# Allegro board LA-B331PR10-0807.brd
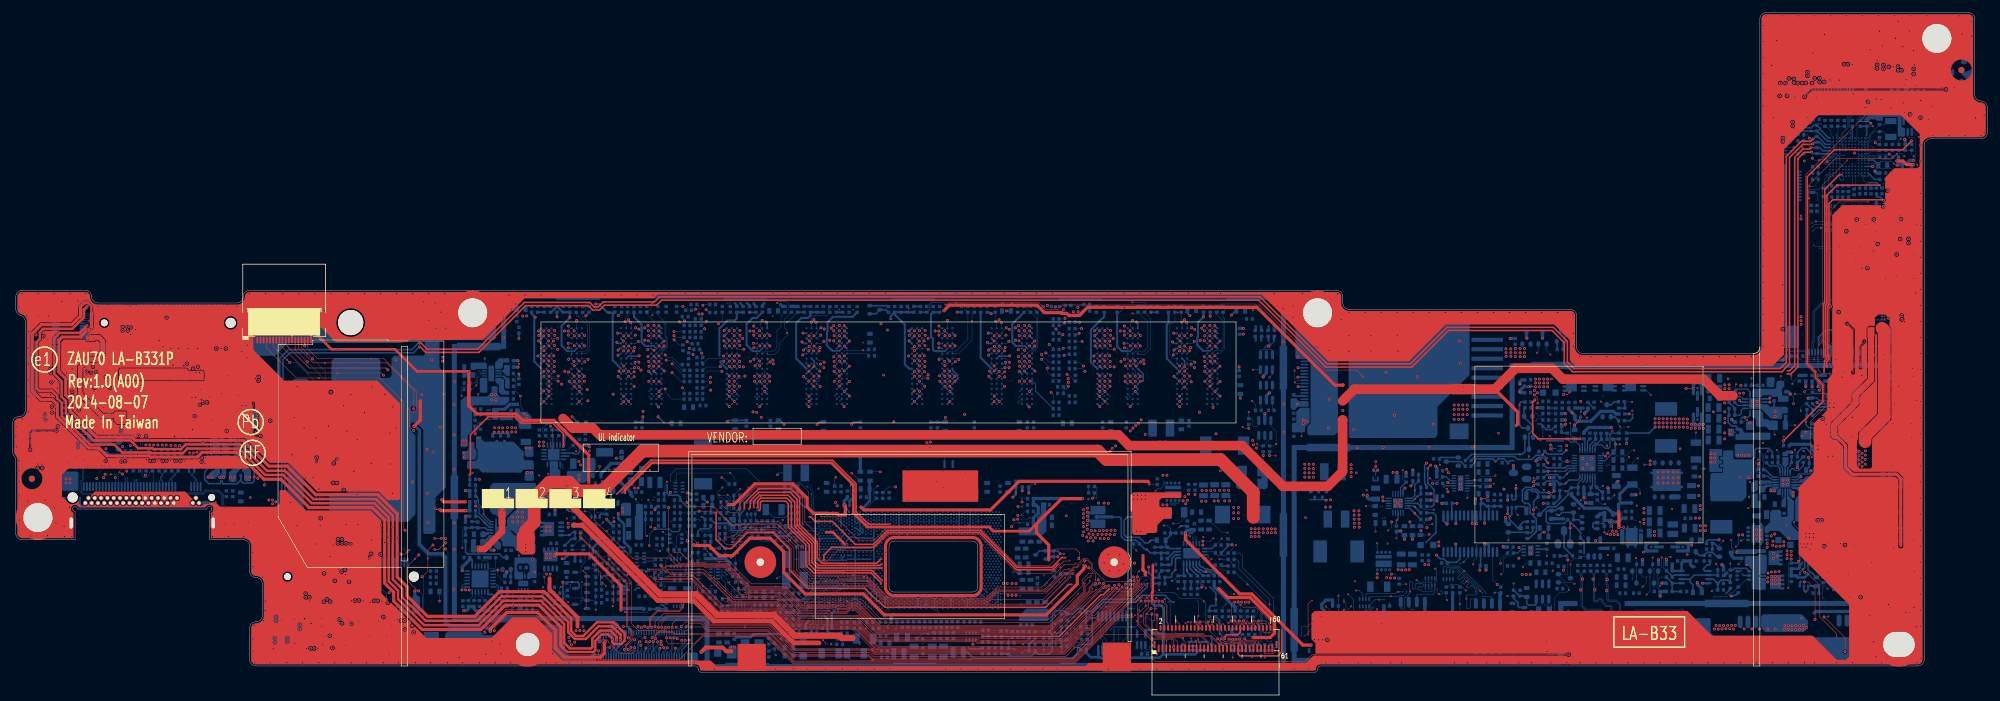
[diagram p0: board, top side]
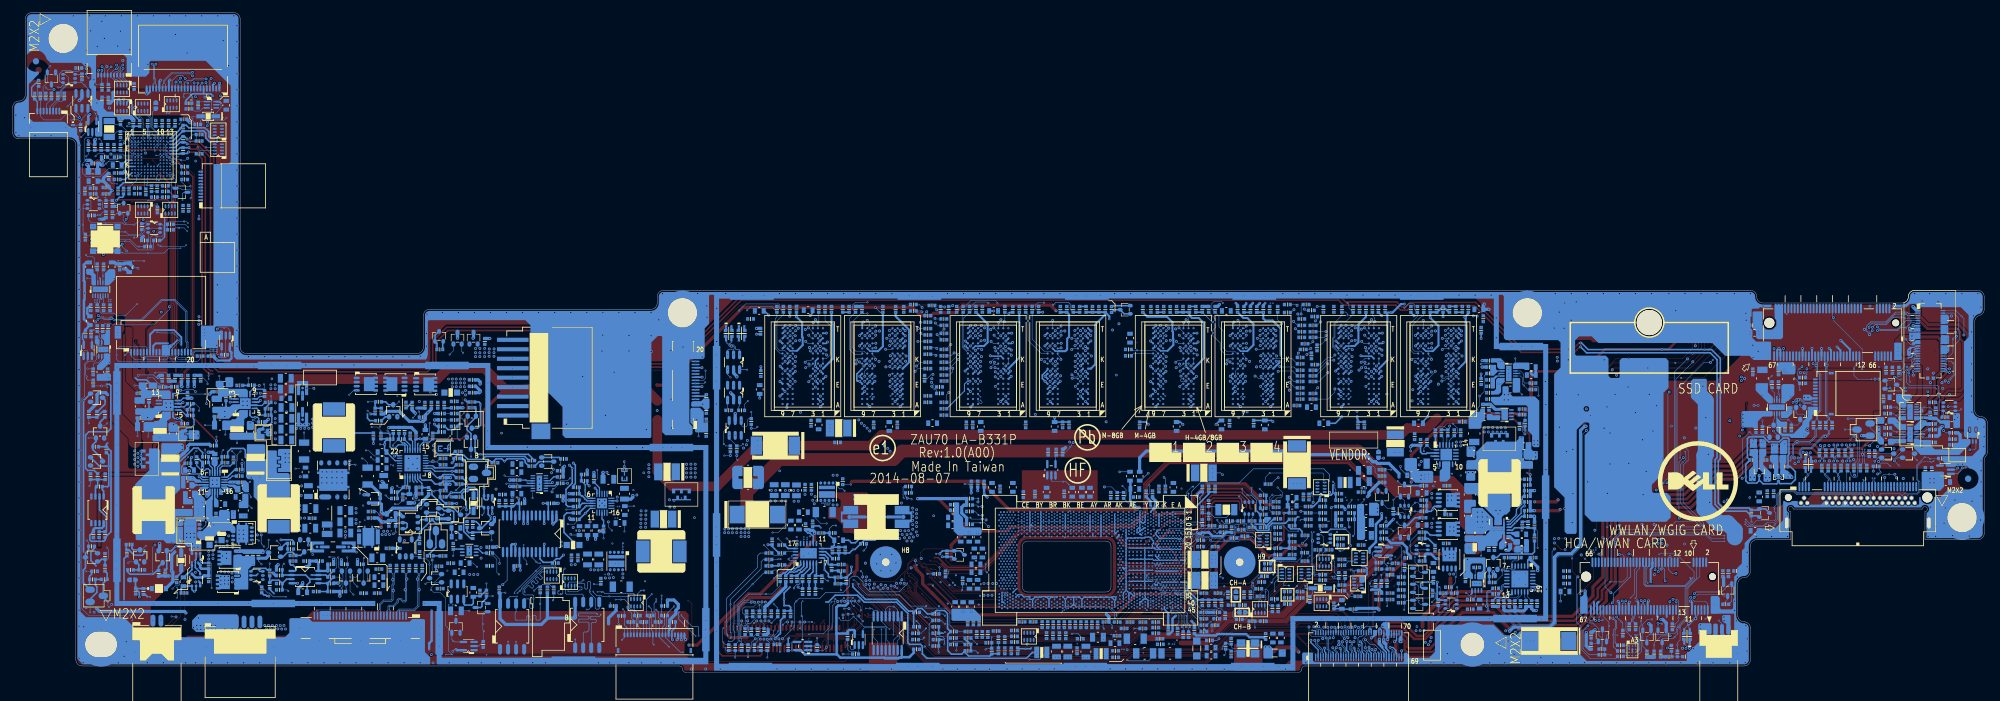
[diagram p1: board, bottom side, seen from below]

Outline 312.5 x 104.5 mm; copper layers: TOP, GND1, IN1, VCC, IN2, IN3, GND2, IN4, GND3, BOTTOM. Coordinates in mm from the lower left corner of the outline.
Outline path: 0,39.5 0,34.91 arc(0.06,34.56) 0.25,34.25 arc(0.44,33.94) 0.5,33.59 0.5,22 arc(0.79,21.29) 1.5,21 9.88,21 9.88,25.46 arc(9.59,26.14) 10.28,25.86 30.73,25.86 arc(31.41,26.14) 31.13,25.46 31.13,21 36.5,21 arc(37.21,20.71) 37.5,20 37.5,16 arc(37.79,15.29) 38.5,15 arc(39.21,14.71) 39.5,14 39.5,9 arc(39.21,8.29) 38.5,8 arc(37.79,7.71) 37.5,7 37.5,2 arc(37.79,1.29) 38.5,1 108,1 arc(108.35,0.85) 108.5,0.5 arc(108.65,0.15) 109,0 206,0 arc(206.35,0.15) 206.5,0.5 arc(206.65,0.85) 207,1 301.5,1 arc(302.21,1.29) 302.5,2 302.5,83.5 arc(302.79,84.21) 303.5,84.5 311.5,84.5 arc(312.21,84.79) 312.5,85.5 312.5,89.5 arc(312.21,90.21) 311.5,90.5 arc(310.79,90.79) 310.5,91.5 310.5,103.5 arc(310.21,104.21) 309.5,104.5 277.5,104.5 arc(276.79,104.21) 276.5,103.5 276.5,51.5 arc(276.21,50.79) 275.5,50.5 248.5,50.5 arc(247.79,50.79) 247.5,51.5 247.5,56.5 arc(247.21,57.21) 246.5,57.5 211.5,57.5 arc(210.79,57.79) 210.5,58.5 210.5,59.5 arc(210.21,60.21) 209.5,60.5 37.5,60.5 arc(36.79,60.21) 36.5,59.5 arc(36.21,58.79) 35.5,58.5 13.5,58.5 arc(12.79,58.79) 12.5,59.5 arc(12.21,60.21) 11.5,60.5 1.5,60.5 arc(0.79,60.21) 0.5,59.5 0.5,57.5 arc(0.71,56.89) 1.25,56.53 arc(1.79,56.18) 2,55.56 2,41.5 arc(1.71,40.79) 1,40.5 arc(0.29,40.21) 0,39.5 ; 138.69,19.97 arc(138.92,20.55) 139.5,20.79 151.9,20.79 arc(152.47,20.55) 152.71,19.97 152.71,13.53 arc(152.47,12.95) 151.9,12.71 139.5,12.71 arc(138.92,12.95) 138.69,13.53 138.69,19.97

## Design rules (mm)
net group DDRCTL_8.5/8.5/7/7/8.5/8.5_16_25: nets M_ODT0 M_ODT2
net group DIFFPAIR0: nets ALS_SMBCLK ALS_SMBDATA
net group DIFFPAIR1: nets CHARGER_SCL CHARGER_SDA
net group DIFFPAIR2: nets CHARGER_SMBCLK CHARGER_SMBDAT
net group DIFFPAIR3: nets CL_CLK CL_DATA
net group DIFFPAIR4: nets CL_CLK_R CL_DATA_R
net group DIFFPAIR6: nets EC_SMCA EC_SMDA
net group DIFFPAIR11: nets PBAT_SMBCLK PBAT_SMBDAT
net group DIFFPAIR12: nets PCH_DDI1_CLK PCH_DDI1_DAT
net group DIFFPAIR13: nets PCH_DDI2_CLK PCH_DDI2_DAT
net group DIFFPAIR14: nets PCH_SMBCLK PCH_SMBDATA
net group DIFFPAIR15: nets SENSOR_I2C_SCL SENSOR_I2C_SDA
net group DIFFPAIR16: nets SMBCLK SMBDATA
net group DIFFPAIR17: nets SML0CLK SML0DATA
net group DIFFPAIR18: nets SML1CLK SML1DATA
net group DIFFPAIR19: nets SML1_SMBCLK SML1_SMBDATA
net group DIFFPAIR20: nets USH_SMBCLK USH_SMBDAT
net group DIFFPAIR22: nets BASE_SMBCLK BASE_SMBDAT
net group EDP_AUX_CONN: nets EDP_AUXN_CONN EDP_AUXP_CONN
net group EDP_TX_P0_CONN: nets EDP_TXN_P0_CONN EDP_TXP_P0_CONN
net group EDP_TX_P1_CONN: nets EDP_TXN_P1_CONN EDP_TXP_P1_CONN
net group PCH_DDI1_0: nets PCH_DDI1_N0 PCH_DDI1_P0
net group PCH_DDI1_1: nets PCH_DDI1_N1 PCH_DDI1_P1
net group PCH_DDI1_2: nets PCH_DDI1_N2 PCH_DDI1_P2
net group PCH_DDI1_3: nets PCH_DDI1_N3 PCH_DDI1_P3
net group PCH_DDI1_AUX: nets PCH_DDI1_AUXN PCH_DDI1_AUXP
net group PCH_DDI2_0_C: nets PCH_DDI2_N0_C PCH_DDI2_P0_C
net group PCH_DDI2_1_C: nets PCH_DDI2_N1_C PCH_DDI2_P1_C
net group PCH_DDI2_2_C: nets PCH_DDI2_N2_C PCH_DDI2_P2_C
net group PCH_DDI2_3_C: nets PCH_DDI2_N3_C PCH_DDI2_P3_C
net group PCH_DDI2_AUX_C: nets PCH_DDI2_AUXN_C PCH_DDI2_AUXP_C
net group PCIE: nets PCIE_PTX_DRX_N5 PCIE_PTX_DRX_P5
net group PCIE_PRX_DTX_5: nets PCIE_PRX_DTX_N5 PCIE_PRX_DTX_P5
net group PCIE_PTX_DRX_3: nets PCIE_PTX_DRX_N3 PCIE_PTX_DRX_P3
net group PCIE_PTX_DRX_6: nets PCIE_PTX_DRX_N6 PCIE_PTX_DRX_P6
net group PCIE_PTX_DRX_6_C: nets PCIE_PTX_DRX_N6_C PCIE_PTX_DRX_P6_C
net group SATA_R1: nets SATA_RN1 SATA_RP1
net group SATA_R1_C: nets SATA_RN1_C SATA_RP1_C
net group SATA_T1: nets SATA_TN1 SATA_TP1
net group SATA_T1_C: nets SATA_TN1_C SATA_TP1_C
net group USB20_0: nets USB20_N0 USB20_P0
net group USB20_1: nets USB20_N1 USB20_P1
net group USB20_5_R: nets USB20_N5_R USB20_P5_R
net group USB20_P6_R: nets USB20_N6_R USB20_P6_R
net group 10: nets LINE1_L LINE1_R REM_DIODE1_N REM_DIODE1_P REM_DIODE2_N REM_DIODE2_P REM_DIODE3_N REM_DIODE3_P XTAL24_IN XTAL24_OUT
net group 12: nets +SIM_PWR CLK_LPC_DEBUG CLK_PCI_MEC CLKOUT_LPC0 CLKOUT_LPC1 HDA_BIT_CLK MSCLK SATA_RCOMP SUSCLK SYSCLK VCCSENSE VCCSENSE_R VSSSENSE VSSSENSE_R XCLK_BIASREF
net group 15: nets PCH_OPIRCOMP PCH_RTCRST# PCH_RTCX1 PCH_RTCX2 PCH_SPI_CLK PCH_SRTCRST# SPI_CLK_ROM1 SPI_CLK_ROM2 SPI_PCH_CLK TPM_SPI_CLK USBRBIAS
net group 20: nets BASE_DC_IN_SS
net group 50H: nets GNSS_SCL GNSS_SDA H_CATERR# H_PROCHOT# H_PROCHOT#_R I2C0_SDA I2C1_SCK I2C1_SDA I2S_MCLK I2S_SCLK PCH_PLTRST# PLT_RST# VCCSTPG_MCP XDP_BPM0# XDP_BPM1# XDP_PWRGD
net group DIFFPAIR23: nets MSDATA
net group GND: nets AGND
net group I2S: nets HDA_RST# HDA_SDOUT HDA_SYNC I2S_SDIN0 I2S_SDOUT I2S_SFRM
net group MG_DATA_DQ-DQ[A_DQ0][0~250MIL]: nets DDR_A_D0 DDR_A_D1 DDR_A_D2 DDR_A_D3 DDR_A_D4 DDR_A_D5 DDR_A_D6 DDR_A_D7
net group MG_DATA_DQ-DQS[A_DQ-DQS0][-400~100MIL]: nets DDR_A_DQS0
net group MG_DATA_DQ-DQS[A_DQ-DQS1][-400~100MIL]: nets DDR_A_DQS1
net group MG_DATA_DQ-DQS[A_DQ-DQS2][-400~100MIL]: nets DDR_A_DQS2
net group MG_DATA_DQ-DQS[A_DQ-DQS3][-400~100MIL]: nets DDR_A_DQS3
net group MG_DATA_DQ-DQS[A_DQ-DQS4][-400~100MIL]: nets DDR_A_DQS4
net group MG_DATA_DQ-DQS[A_DQ-DQS5][-400~100MIL]: nets DDR_A_D40 DDR_A_D41 DDR_A_D42 DDR_A_D43 DDR_A_D44 DDR_A_D45 DDR_A_D46 DDR_A_D47 DDR_A_DQS5
net group MG_DATA_DQ-DQS[A_DQ-DQS6][-400~100MIL]: nets DDR_A_DQS6
net group MG_DATA_DQ-DQS[A_DQ-DQS7][-400~100MIL]: nets DDR_A_DQS7
net group MG_DATA_DQ-DQS[A_DQ-DQS#0][-400~100MIL]: nets DDR_A_DQS#0
net group MG_DATA_DQ-DQS[A_DQ-DQS#1][-400~100MIL]: nets DDR_A_D8 DDR_A_D9 DDR_A_D10 DDR_A_D11 DDR_A_D12 DDR_A_D13 DDR_A_D14 DDR_A_D15 DDR_A_DQS#1
net group MG_DATA_DQ-DQS[A_DQ-DQS#2][-400~100MIL]: nets DDR_A_D16 DDR_A_D17 DDR_A_D18 DDR_A_D19 DDR_A_D20 DDR_A_D21 DDR_A_D22 DDR_A_D23 DDR_A_DQS#2
net group MG_DATA_DQ-DQS[A_DQ-DQS#3][-400~100MIL]: nets DDR_A_D24 DDR_A_D25 DDR_A_D26 DDR_A_D27 DDR_A_D28 DDR_A_D29 DDR_A_D30 DDR_A_D31 DDR_A_DQS#3
net group MG_DATA_DQ-DQS[A_DQ-DQS#4][-400~100MIL]: nets DDR_A_D32 DDR_A_D33 DDR_A_D34 DDR_A_D35 DDR_A_D36 DDR_A_D37 DDR_A_D38 DDR_A_D39 DDR_A_DQS#4
net group MG_DATA_DQ-DQS[A_DQ-DQS#5][-400~100MIL]: nets DDR_A_DQS#5
net group MG_DATA_DQ-DQS[A_DQ-DQS#6][-400~100MIL]: nets DDR_A_D48 DDR_A_D49 DDR_A_D50 DDR_A_D51 DDR_A_D52 DDR_A_D53 DDR_A_D54 DDR_A_D55 DDR_A_DQS#6
net group MG_DATA_DQ-DQS[A_DQ-DQS#7][-400~100MIL]: nets DDR_A_D56 DDR_A_D57 DDR_A_D58 DDR_A_D59 DDR_A_D60 DDR_A_D61 DDR_A_D62 DDR_A_D63 DDR_A_DQS#7
net group MG_DATA_DQ-DQS[B_DQ-DQS0][-400~100MIL]: nets DDR_B_DQS0
net group MG_DATA_DQ-DQS[B_DQ-DQS1][-400~100MIL]: nets DDR_B_DQS1
net group MG_DATA_DQ-DQS[B_DQ-DQS2][-400~100MIL]: nets DDR_B_DQS2
net group MG_DATA_DQ-DQS[B_DQ-DQS3][-400~100MIL]: nets DDR_B_DQS3
net group MG_DATA_DQ-DQS[B_DQ-DQS4][-400~100MIL]: nets DDR_B_DQS4
net group MG_DATA_DQ-DQS[B_DQ-DQS5][-400~100MIL]: nets DDR_B_D40 DDR_B_D41 DDR_B_D42 DDR_B_D43 DDR_B_D44 DDR_B_D45 DDR_B_D46 DDR_B_D47 DDR_B_DQS5
net group MG_DATA_DQ-DQS[B_DQ-DQS6][-400~100MIL]: nets DDR_B_DQS6
net group MG_DATA_DQ-DQS[B_DQ-DQS7][-400~100MIL]: nets DDR_B_DQS7
net group MG_DATA_DQ-DQS[B_DQ-DQS#0][-400~100MIL]: nets DDR_B_D0 DDR_B_D1 DDR_B_D2 DDR_B_D3 DDR_B_D4 DDR_B_D5 DDR_B_D6 DDR_B_D7 DDR_B_DQS#0
net group MG_DATA_DQ-DQS[B_DQ-DQS#1][-400~100MIL]: nets DDR_B_D8 DDR_B_D9 DDR_B_D10 DDR_B_D11 DDR_B_D12 DDR_B_D13 DDR_B_D14 DDR_B_D15 DDR_B_DQS#1
net group MG_DATA_DQ-DQS[B_DQ-DQS#2][-400~100MIL]: nets DDR_B_D16 DDR_B_D17 DDR_B_D18 DDR_B_D19 DDR_B_D20 DDR_B_D21 DDR_B_D22 DDR_B_D23 DDR_B_DQS#2
net group MG_DATA_DQ-DQS[B_DQ-DQS#3][-400~100MIL]: nets DDR_B_D24 DDR_B_D25 DDR_B_D26 DDR_B_D27 DDR_B_D28 DDR_B_D29 DDR_B_D30 DDR_B_D31 DDR_B_DQS#3
net group MG_DATA_DQ-DQS[B_DQ-DQS#4][-400~100MIL]: nets DDR_B_D32 DDR_B_D33 DDR_B_D34 DDR_B_D35 DDR_B_D36 DDR_B_D37 DDR_B_D38 DDR_B_D39 DDR_B_DQS#4
net group MG_DATA_DQ-DQS[B_DQ-DQS#5][-400~100MIL]: nets DDR_B_DQS#5
net group MG_DATA_DQ-DQS[B_DQ-DQS#6][-400~100MIL]: nets DDR_B_D48 DDR_B_D49 DDR_B_D50 DDR_B_D51 DDR_B_D52 DDR_B_D53 DDR_B_D54 DDR_B_D55 DDR_B_DQS#6
net group MG_DATA_DQ-DQS[B_DQ-DQS#7][-400~100MIL]: nets DDR_B_D56 DDR_B_D57 DDR_B_D58 DDR_B_D59 DDR_B_D60 DDR_B_D61 DDR_B_D62 DDR_B_D63 DDR_B_DQS#7
net group MG_STROBE_CK-DQS[A_CK0-DQS][-1500~2500MILMIL]: nets M_CLK_A_DDR0
net group MG_STROBE_CK-DQS[A_CK#0-DQS][-1500~2500MILMIL]: nets M_CLK_A_DDR#0
net group MG_STROBE_CK-DQS[B_CK0-DQS][-1500~2500MILMIL]: nets M_CLK_B_DDR0
net group MG_STROBE_CK-DQS[B_CK#0-DQS][-1500~2500MILMIL]: nets M_CLK_B_DDR#0
net group POWER-10: nets +1.05VS_VCCST +3V_PCH_DSW +PCH_VCCDSW +V1.05A_DCPSUS1 +V1.05A_DCPSUS2 +V1.05A_DCPSUS3 +V1.05S_APLL +V1.05S_APLLOPI +V1.05S_AUSB +VCCIO_OUT +VR_CAP +VS_LPSS_SDIO V_DDR_REFA_R V_DDR_REFB_R
net group POWER-15: nets +V1.05S_AUSB3PLL +V1.05S_MPHY_PCIE CFG_RCOMP PCIE_RCOMP PROC_OPI_COMP SM_RCOMP0 SM_RCOMP1 SM_RCOMP2 TD_IREF
net group POWER-20: nets +1.5VS +1.5VSP +5VS_AUDIO +EDP_COM +VCCIOA_OUT
net group SIM: nets UIM_CLK UIM_DATA UIM_DET# UIM_RESET
net group SPI: nets PCH_SPI_CS0# PCH_SPI_CS1# PCH_SPI_CS2# PCH_SPI_IO2 PCH_SPI_IO3 PCH_SPI_SI PCH_SPI_SO SPI_IO2_ROM1 SPI_IO2_ROM2 SPI_IO3_ROM1 SPI_IO3_ROM2 SPI_PCH_CS0# SPI_PCH_CS1# SPI_PCH_IO2 SPI_PCH_IO3 SPI_PCH_SI SPI_PCH_SO SPI_SI_ROM1 SPI_SI_ROM2 SPI_SO_ROM1 SPI_SO_ROM2 TPM_SPI_SI TPM_SPI_SO
net group SPK: nets SPK_L+_C SPK_L-_C SPK_R+_C SPK_R-_C
net group SVID: nets H_CPU_SVIDALRT# H_CPU_SVIDCLK H_CPU_SVIDDAT VR_SVID_ALRT# VR_SVID_CLK VR_SVID_DAT
net group USB30: nets USB3RN1 USB3RN1_C USB3RN1_RP USB3RP1 USB3RP1_C USB3RP1_RP USB3TN1 USB3TP1
nets with their own width: min track width 0.203; nets +3.3V_M +3VALW_EC +3VNS_PWR +3VS_AUDIO +3VS_TS
nets with their own width: min track width 0.254; nets +1.05V_SATAMODPHY_D +1.05VDX_MODPHY_D +1.05VS +1.05VS_XDP +1.35V_DDR +1.35VP +3VS_TPM +RTC_VCCSUS +RTCVCC +RTCVCC_R +V1.05A_AOSCSUS +V1.05S_AXCK_DCB +V1.05S_AXCK_LCPLL +V1.05S_MPHY_SATA +V1.05S_MPHY_USB3 ACAV_IN B+ BATT_PRS# BQ24777_REGN COMP CSSN_1 CSSP_1 FB HOT# I_ADP I_SYS IMON ISUMN ISUMP N45067794 N45067802 N45067875 N50817758 N50817763 N50817815 N50817876 N50817886 N50817889 N50817892 N50817943 N50817947 N52711885 N115444004 N115444070 N115444179 NTC PBAT_PRES# V_SYS VGATE VR_ON
nets with their own width: min track width 0.381; nets +LCDVDD +V1.05S_ASATA3PLL +VCHGR
nets with their own width: min track width 0.406; nets +3V_PCH
nets with their own width: min track width 0.508; nets +0.675VS +1.05VA +1.8VS +3VALW +3VS +5VALW +5VS +DC_IN +PBATT +VCC_CORE +VREFCA +VREFDQ_A +VREFDQ_B BATDRV# GND N50817748 N52697183 VBATT
nets with their own width: min track width 0.635; nets +1.05V_USB3MODPHY +5V_DOCK N53478114
nets with their own width: min track width 0.762; nets +1.05V_SATAMODPHY
nets with their own width: min track width 1.016; nets +1.05VDX_MODPHY +3.3VDX_SSD +3VS_CAM CHG_LGATE CHG_SW CHG_UGATE LAGTE LG_3V LG_5V LX_3V LX_5V PHASE UAGTE UG_3V UG_5V
nets with their own width: min track width 2.032; nets +3VS_WLAN
nets with their own width: min track width 2.54; nets +3VS_WWAN

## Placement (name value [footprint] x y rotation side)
C1  0.1U_0402_10V7K  [C_0402]  192.44 8.81 90 bottom
C2  0.1U_0402_10V7K  [C_0402]  193.08 3.45 90 bottom
C4  10U_0603_6.3V6M  [C_0603]  255.24 15.08 180 bottom
C5  .1U_0402_16V7K  [C_0402]  255.26 12.54 180 bottom
C6  10U_0603_6.3V6M  [C_0603]  255.24 13.81 180 bottom
C7  0.1U_0402_10V7K  [C_0402]  247.69 16.93 270 bottom
C8  0.1U_0402_10V7K  [C_0402]  248.7 16.93 270 bottom
C9  0.1U_0402_10V7K  [C_0402]  249.72 16.93 270 bottom
C10  0.1U_0402_10V7K  [C_0402]  250.73 16.93 270 bottom
C11  1U_0603_25V6K  [C_0603]  239.61 13.35 270 bottom
C12  0.1U_0402_25V6  [C_0402]  244.38 13.25 0 bottom
C13  0.1U_0402_10V7K  [C_0402]  251.75 16.93 270 bottom
C14  0.1U_0402_10V7K  [C_0402]  252.77 16.93 270 bottom
C16  22U_0603_6.3V6M  [C_0603]  36.1 27.08 90 bottom
C17  0.1U_0402_10V7K  [C_0402]  33.82 27.83 90 bottom
C18  22U_0603_6.3V6M  [C_0603]  7.3 30.15 180 bottom
C19  0.1U_0402_10V7K  [C_0402]  9.82 31.51 90 bottom
C20  22U_0603_6.3V6M  [C_0603]  37.46 22.41 180 bottom
C21  0.1U_0402_10V7K  [C_0402]  40.98 16.07 270 bottom
C22  22U_0603_6.3V6M  [C_0603]  66.14 12.79 0 bottom
C23  0.1U_0402_10V7K  [C_0402]  66.13 14.06 0 bottom
C29  .1U_0402_16V7K  [C_0402]  14.01 48.3 270 bottom
C30  47P_0402_50V8J  [C_0402]  15.02 48.3 270 bottom
C31  4.7U_0603_6.3V6K  [C_0603]  36.14 53.78 0 bottom
C32  0.01U_0402_16V7K  [C_0402]  36.66 54.96 0 bottom
C33  0.1U_0402_10V7K  [C_0402]  32.04 39.16 270 bottom
C34  4700P_0402_16V7K  [C_0402]  15.33 40.99 0 bottom
C35  0.1U_0402_10V7K  [C_0402]  33.06 48.05 270 bottom
C74  0.1U_0402_10V7K  [C_0402]  233.46 26.31 90 bottom
C75  4700P_0402_25V7K  [C_0402]  235.49 26.31 90 bottom
C76  2200P_0402_25V7K  [C_0402]  232.24 16.86 0 bottom
C77  2200P_0402_25V7K  [C_0402]  227.07 17.3 180 bottom
C78  2200P_0402_25V7K  [C_0402]  227.82 26.76 180 bottom
C79  0.1U_0402_10V7K  [C_0402]  232.4 26.76 180 bottom
C90  0.1U_0402_10V7K  [C_0402]  245.51 16.79 180 bottom
C92  1U_0402_6.3V6K  [C_0402]  234.53 28.16 0 bottom
C93  2200P_0402_25V7K  [C_0402]  232.24 29.43 0 bottom
C94  2200P_0402_25V7K  [C_0402]  232.24 30.45 0 bottom
C95  1U_0402_6.3V6K  [C_0402]  226.3 27.91 180 bottom
C96  1U_0402_6.3V6K  [C_0402]  37.12 48.05 270 bottom
C97  10U_0603_6.3V6M  [C_0603]  71.47 47.08 0 bottom
C98  2200P_0402_25V7K  [C_0402]  72.38 45.81 180 bottom
C99  2200P_0402_25V7K  [C_0402]  72.38 44.8 180 bottom
C100  0.1U_0402_10V7K  [C_0402]  78.32 49.37 0 bottom
C101  0.1U_0402_10V7K  [C_0402]  300.14 58.21 270 bottom
C102  0.1U_0402_10V7K  [C_0402]  9.05 41.19 270 bottom
C103  1U_0402_6.3V6K  [C_0402]  78.32 43.27 0 bottom
C104  2200P_0402_25V7K  [C_0402]  299.12 63.77 90 bottom
C105  2200P_0402_25V7K  [C_0402]  298.11 63.77 90 bottom
C106  0.1U_0402_10V7K  [C_0402]  89.7 35.96 90 bottom
C107  10U_0603_6.3V6M  [C_0603]  90.4 31.21 0 bottom
C108  1000P_0402_25V8J  [C_0402]  86.4 37.48 90 bottom
C109  0.1U_0402_10V7K  [C_0402]  83.35 37.48 90 bottom
C110  0.1U_0402_10V7K  [C_0402]  297.09 58.21 270 bottom
C111  1000P_0402_50V7K  [C_0402]  88.68 35.96 90 bottom
C112  0.1U_0402_10V7K  [C_0402]  300.98 54.08 270 bottom
C113  2200P_0402_25V7K  [C_0402]  34.07 45.1 90 bottom
C114  2200P_0402_25V7K  [C_0402]  33.06 45.1 90 bottom
C115  0.1U_0402_10V7K  [C_0402]  237.48 16.86 180 bottom
C116  0.1U_0402_10V7K  [C_0402]  36.61 38.91 270 bottom
C117  0.1U_0402_10V7K  [C_0402]  226.3 31.92 180 bottom
C118  0.1U_0402_10V7K  [C_0402]  9.13 39.34 180 bottom
C119  10U_0603_6.3V6M  [C_0603]  233.4 32.99 180 bottom
C120  0.1U_0402_10V7K  [C_0402]  242.72 17.28 0 bottom
C121  2200P_0402_25V7K  [C_0402]  242.78 19.5 90 bottom
C122  0.1U_0402_10V7K  [C_0402]  85.08 29.56 0 bottom
C123  10U_0603_6.3V6M  [C_0603]  88.75 28.41 0 bottom
C124  0.047U_0402_25V7K  [C_0402]  88.73 27.27 0 bottom
C125  0.1U_0402_10V7K  [C_0402]  84.92 24.99 0 bottom
C126  10U_0603_6.3V6M  [C_0603]  88.75 23.33 0 bottom
C127  0.047U_0402_25V7K  [C_0402]  87.41 20.11 270 bottom
C128  0.1U_0402_10V7K  [C_0402]  85.18 20.41 0 bottom
C129  10U_0603_6.3V6M  [C_0603]  87.67 15.91 90 bottom
C130  0.047U_0402_25V7K  [C_0402]  84.82 13.48 0 bottom
C131  0.1U_0402_10V7K  [C_0402]  9.13 42.77 180 bottom
C132  1000P_0402_25V8J  [C_0402]  15.33 37.69 0 bottom
C133  2200P_0402_25V7K  [C_0402]  15.33 42 0 bottom
C134  0.1U_0402_10V7K  [C_0402]  16.43 43.78 270 bottom
C135  220P_0402_25V8K  [C_0402]  15.33 38.7 0 bottom
C136  0.1U_0402_10V7K  [C_0402]  9.13 36.42 180 bottom
C139  0.1U_0402_10V7K  [C_0402]  299.04 80.61 0 bottom
C140  0.1U_0402_10V7K  [C_0402]  292.31 75.81 0 bottom
C141  0.1U_0402_10V7K  [C_0402]  295.49 79.09 0 bottom
C142  0.1U_0402_10V7K  [C_0402]  283.45 82.14 180 bottom
C143  0.1U_0402_10V7K  [C_0402]  297.27 76.8 0 bottom
C144  0.1U_0402_10V7K  [C_0402]  287.87 76.17 0 bottom
C145  0.1U_0402_10V7K  [C_0402]  297.27 75.79 0 bottom
C146  0.1U_0402_10V7K  [C_0402]  292.31 76.7 0 bottom
C147  0.1U_0402_10V7K  [C_0402]  291.12 86.5 90 bottom
C148  0.1U_0402_10V7K  [C_0402]  287.82 86.5 90 bottom
C149  0.1U_0402_10V7K  [C_0402]  293.41 86.5 90 bottom
C150  4700P_0402_25V7K  [C_0402]  295.49 81.63 0 bottom
C154  2200P_0402_50V7K  [C_0402]  285.53 82.19 90 bottom
C155  2200P_0402_50V7K  [C_0402]  285.53 84.88 270 bottom
C156  2200P_0402_50V7K  [C_0402]  285.53 85.74 90 bottom
C157  22P_0402_50V8J  [C_0402]  295.44 86.76 90 bottom
C158  27P_0402_50V8J  [C_0402]  295.44 85.64 270 bottom
C159  0.1U_0402_10V7K  [C_0402]  283.45 84.17 180 bottom
C160  4.7U_0603_6.3V6K  [C_0603]  295.25 80.36 0 bottom
C161  1U_0402_6.3V4Z  [C_0402]  288.83 86.5 90 bottom
C162  4.7P_0402_50V8C  [C_0402]  289.63 76.15 90 bottom
C163  100P_0402_50V8J  [C_0402]  244.43 51.15 0 bottom
C164  100P_0402_50V8J  [C_0402]  164.63 18.31 90 bottom
C165  0.1U_0402_25V6K  [C_0402]  297.72 74.72 270 bottom
C166  100P_0402_50V8J  [C_0402]  37.37 25.7 270 bottom
C168  100P_0402_50V8J  [C_0402]  138.59 57.02 90 bottom
C193  .1U_0402_16V7K  [C_0402]  202.73 43.05 90 bottom
C194  .1U_0402_16V7K  [C_0402]  202.74 39.19 90 bottom
C197  0.1U_0402_10V7K  [C_0402]  78.32 44.29 0 bottom
C198  0.1U_0402_10V7K  [C_0402]  295.57 64.69 270 bottom
C199  0.1U_0402_10V7K  [C_0402]  5.04 36.03 0 bottom
C200  10P_0402_50V8J  [C_0402]  5.95 36.92 180 bottom
C203  0.1U_0402_10V7K  [C_0402]  55.66 6.75 90 bottom
C204  0.1U_0402_10V7K  [C_0402]  56.68 6.75 90 bottom
C205  0.47U_0402_6.3V6K  [C_0402]  115.05 26 180 bottom
C214  .1U_0402_16V7K  [C_0402]  252.47 19.64 0 bottom
C215  .1U_0402_16V7K  [C_0402]  255 16.35 180 bottom
C216  470U_X_2VY_R9M  [C_X]  109.26 35.86 270 bottom
C217  470U_X_2VY_R9M  [C_X]  188.81 35.91 0 bottom
C218  2200P_0402_25V7K  [C_0402]  299.76 48.05 270 bottom
C219  0.1U_0402_10V7K  [C_0402]  297.47 47.13 90 bottom
C220  0.1U_0402_10V7K  [C_0402]  297.37 53.99 90 bottom
C221  330U_B2_2.5VM_R9M  [C_B2]  125.19 17.87 0 bottom
C222  330U_B2_2.5VM_R9M  [C_B2]  125.19 14.57 0 bottom
C223  330U_B2_2.5VM_R9M  [C_B2]  125.36 31.59 0 bottom
C224  100P_0402_50V8J  [C_0402]  138.72 27.58 90 bottom
C225  100P_0402_50V8J  [C_0402]  153.5 5.71 0 bottom
C234  0.1U_0402_16V4Z  [C_0402]  78.28 11.34 270 bottom
C235  0.01U_0402_16V7K  [C_0402]  72.34 18.16 180 bottom
C236  0.1U_0402_10V7K  [C_0402]  77.35 13.31 0 bottom
C237  0.1U_0402_10V7K  [C_0402]  77.34 12.42 0 bottom
C238  2200P_0402_25V7K  [C_0402]  81.37 11.52 0 bottom
C239  0.1U_0402_10V7K  [C_0402]  81.37 10 0 bottom
C240  0.1U_0402_10V7K  [C_0402]  82.59 15.28 270 bottom
C241  1U_0402_6.3V6K  [C_0402]  284.15 89.26 0 bottom
C242  33P_0402_50V8J  [C_0402]  256.5 12.54 0 bottom
C243  33P_0402_50V8J  [C_0402]  202.73 41.94 270 bottom
C244  .1U_0402_16V7K  [C_0402]  202.75 38.3 270 bottom
C245  15P_0402_50V8J  [C_0402]  8.8 31.51 90 bottom
C246  15P_0402_50V8J  [C_0402]  34.83 27.83 90 bottom
C247  33P_0402_50V8J  [C_0402]  41.86 16.07 270 bottom
C248  33P_0402_50V8J  [C_0402]  66.13 15.08 0 bottom
C249  33P_0402_50V8J  [C_0402]  16.04 48.3 270 bottom
C250  33P_0402_50V8J  [C_0402]  234.48 26.31 90 bottom
C251  33P_0402_50V8J  [C_0402]  285.79 47.03 270 bottom
C252  33P_0402_50V8J  [C_0402]  284.77 47.03 270 bottom
C253  33P_0402_50V8J  [C_0402]  283.75 47.03 270 bottom
C255  10U_0603_6.3V6M  [C_0603]  278.7 90.53 270 bottom
C256  0.1U_0402_10V7K  [C_0402]  289.6 72.79 90 bottom
C257  0.1U_0402_10V7K  [C_0402]  295.82 76.71 270 bottom
C258  0.1U_0402_10V7K  [C_0402]  295.49 78.07 0 bottom
C259  0.1U_0402_10V7K  [C_0402]  294.08 76.71 270 bottom
C260  330U_D2E_6.3VM_R25M  [C_D2E]  66.25 4.95 0 bottom
C261  0.22U_0402_10V6K  [C_0402]  283.14 90.31 270 bottom
C262  1U_0402_6.3V6K  [C_0402]  309.01 90.82 90 bottom
C263  0.1U_0402_10V7K  [C_0402]  74.04 39.41 270 bottom
C264  2200P_0402_25V7K  [C_0402]  78.88 41.52 90 bottom
C265  0.1U_0402_10V7K  [C_0402]  79.79 41.52 90 bottom
C266  47P_0402_50V8J  [C_0402]  66.14 16.04 0 bottom
C267  47P_0402_50V8J  [C_0402]  40.13 16.05 180 bottom
C268  47P_0402_50V8J  [C_0402]  79.78 56.47 270 bottom
C269  47P_0402_50V8J  [C_0402]  90.64 37.79 270 bottom
C270  47P_0402_50V8J  [C_0402]  195.27 55.97 0 bottom
C271  47P_0402_50V8J  [C_0402]  181.49 36.42 0 bottom
C272  0.1U_0402_10V7K  [C_0402]  301.06 76.68 270 bottom
C273  0.1U_0402_10V7K  [C_0402]  48.21 2.47 180 bottom
CA53  1000P_0402_25V8J  [C_0402]  33.36 32.61 0 bottom
CA54  1000P_0402_25V8J  [C_0402]  32.5 32.61 180 bottom
CA55  1000P_0402_25V8J  [C_0402]  35.8 33.62 180 bottom
CA56  1000P_0402_25V8J  [C_0402]  36.66 33.62 0 bottom
CA57  27P_0402_50V8J  [C_0402]  29.69 45.77 180 bottom
CC1  0.1U_0402_10V7K  [C_0402]  148.63 34.42 90 bottom
CC2  10U_0603_6.3V6M  [C_0603]  144.82 27.83 90 bottom
CC3  10U_0603_6.3V6M  [C_0603]  157.52 28.59 90 bottom
CC4  10U_0603_6.3V6M  [C_0603]  143.29 27.83 90 bottom
CC5  10U_0603_6.3V6M  [C_0603]  148.88 27.83 90 bottom
CC6  10U_0603_6.3V6M  [C_0603]  142.02 27.83 90 bottom
CC7  10U_0603_6.3V6M  [C_0603]  154.21 28.59 90 bottom
CC8  2.2U_0402_6.3V6M  [C_0402]  146.09 27.81 90 bottom
CC9  2.2U_0402_6.3V6M  [C_0402]  156.25 28.58 90 bottom
CC10  2.2U_0402_6.3V6M  [C_0402]  152.56 27.69 90 bottom
CC11  2.2U_0402_6.3V6M  [C_0402]  150.72 27.76 90 bottom
CD1  .047U_0402_16V7K  [C_0402]  174.79 57.04 90 bottom
CD2  .047U_0402_16V7K  [C_0402]  188.45 57.07 90 bottom
CD3  .047U_0402_16V7K  [C_0402]  172.76 57.96 270 bottom
CD4  .047U_0402_16V7K  [C_0402]  182.92 57.96 270 bottom
CD5  0.1U_0402_25V6  [C_0402]  184.92 57.04 90 bottom
CD6  1U_0402_6.3V6K  [C_0402]  180.12 57.04 90 bottom
CD7  1U_0402_6.3V6K  [C_0402]  176.24 39.65 270 bottom
CD8  1U_0402_6.3V6K  [C_0402]  194.14 53.56 90 bottom
CD9  1U_0402_6.3V6K  [C_0402]  189.52 57.04 90 bottom
CD10  1U_0402_6.3V6K  [C_0402]  186.15 39.91 270 bottom
CD11  1U_0402_6.3V6K  [C_0402]  194.09 47.8 270 bottom
CD12  10U_0603_6.3V6M  [C_0603]  194.28 44.1 90 bottom
CD13  10U_0603_6.3V6M  [C_0603]  185.9 57.37 0 bottom
CD14  1U_0402_6.3V6K  [C_0402]  181.14 57.04 90 bottom
CD15  1U_0402_6.3V6K  [C_0402]  161.58 39.65 270 bottom
CD16  10U_0603_6.3V6M  [C_0603]  193.65 57.24 0 bottom
CD17  10U_0603_6.3V6M  [C_0603]  184.95 39.89 270 bottom
CD18  330U_B2_2VM_R15M  [C_B2]  180.4 38.69 180 bottom
CD19  .047U_0402_16V7K  [C_0402]  146.7 57.04 90 bottom
CD20  .047U_0402_16V7K  [C_0402]  145.68 57.04 90 bottom
CD21  .047U_0402_16V7K  [C_0402]  139.58 57.96 270 bottom
CD22  .047U_0402_16V7K  [C_0402]  153.2 57.96 270 bottom
CD23  0.1U_0402_25V6  [C_0402]  155.48 57.04 90 bottom
CD24  1U_0402_6.3V6K  [C_0402]  160.56 39.65 270 bottom
CD25  1U_0402_6.3V6K  [C_0402]  150.15 57.04 90 bottom
CD26  1U_0402_6.3V6K  [C_0402]  145.32 39.65 270 bottom
CD27  1U_0402_6.3V6K  [C_0402]  152.18 39.65 270 bottom
CD28  1U_0402_6.3V6K  [C_0402]  146.34 39.65 270 bottom
CD29  1U_0402_6.3V6K  [C_0402]  154.21 57.02 90 bottom
CD30  10U_0603_6.3V6M  [C_0603]  159.29 39.64 270 bottom
CD31  10U_0603_6.3V6M  [C_0603]  147.61 39.64 270 bottom
CD32  1U_0402_6.3V6K  [C_0402]  159.04 57.04 90 bottom
CD33  1U_0402_6.3V6K  [C_0402]  172.5 39.65 270 bottom
CD34  10U_0603_6.3V6M  [C_0603]  173.77 39.64 270 bottom
CD35  10U_0603_6.3V6M  [C_0603]  157.96 57.24 180 bottom
CD36  .047U_0402_16V7K  [C_0402]  133.64 57.02 90 bottom
CD37  .047U_0402_16V7K  [C_0402]  118.65 57.04 90 bottom
CD38  .047U_0402_16V7K  [C_0402]  114.59 57.94 270 bottom
CD39  .047U_0402_16V7K  [C_0402]  115.61 57.94 270 bottom
CD40  0.1U_0402_25V6  [C_0402]  129.32 57.02 90 bottom
CD41  1U_0402_6.3V6K  [C_0402]  119.92 39.91 270 bottom
CD42  1U_0402_6.3V6K  [C_0402]  116.62 57.02 90 bottom
CD43  1U_0402_6.3V6K  [C_0402]  134.15 39.65 270 bottom
CD44  1U_0402_6.3V6K  [C_0402]  130.34 57.04 90 bottom
CD45  1U_0402_6.3V6K  [C_0402]  117.64 57.02 90 bottom
CD46  1U_0402_6.3V6K  [C_0402]  116.11 39.91 270 bottom
CD47  10U_0603_6.3V6M  [C_0603]  119.73 57.24 0 bottom
CD48  10U_0603_6.3V6M  [C_0603]  128.31 39.64 270 bottom
CD49  1U_0402_6.3V6K  [C_0402]  131.35 57.02 90 bottom
CD50  1U_0402_6.3V6K  [C_0402]  132.37 57.04 90 bottom
CD51  10U_0603_6.3V6M  [C_0603]  121.19 39.89 270 bottom
CD52  10U_0603_6.3V6M  [C_0603]  135.67 52.23 90 bottom
CD53  330U_B2_2VM_R15M  [C_B2]  93.69 37.6 90 bottom
CD54  .047U_0402_16V7K  [C_0402]  98.33 57.02 90 bottom
CD55  .047U_0402_16V7K  [C_0402]  88.17 57.04 90 bottom
CD56  .047U_0402_16V7K  [C_0402]  95.29 57.96 270 bottom
CD57  .047U_0402_16V7K  [C_0402]  82.13 57.96 270 bottom
CD58  0.1U_0402_25V6  [C_0402]  97.32 57.04 90 bottom
CD59  1U_0402_6.3V6K  [C_0402]  99.35 57.04 90 bottom
CD60  1U_0402_6.3V6K  [C_0402]  83.55 39.7 180 bottom
CD61  1U_0402_6.3V6K  [C_0402]  80.11 53.72 90 bottom
CD62  1U_0402_6.3V6K  [C_0402]  80.11 46.51 270 bottom
CD63  1U_0402_6.3V6K  [C_0402]  96.37 57.02 90 bottom
CD64  1U_0402_6.3V6K  [C_0402]  98.59 39.65 270 bottom
CD65  10U_0603_6.3V6M  [C_0603]  81.18 57.5 180 bottom
CD66  10U_0603_6.3V6M  [C_0603]  89.32 39.45 0 bottom
CD67  1U_0402_6.3V6K  [C_0402]  99.6 39.65 270 bottom
CD68  1U_0402_6.3V6K  [C_0402]  91.22 57.04 90 bottom
CD69  10U_0603_6.3V6M  [C_0603]  104.31 39.45 0 bottom
CD70  10U_0603_6.3V6M  [C_0603]  114.34 39.89 270 bottom
CD71  .1U_0402_16V7K  [C_0402]  160.06 57.04 90 bottom
CD72  0.022U_0402_16V7K  [C_0402]  84.11 57.96 270 bottom
CD73  0.022U_0402_16V7K  [C_0402]  143.65 57.96 270 bottom
CD74  0.022U_0402_16V7K  [C_0402]  125.26 57.96 270 bottom
CD75  1U_0402_6.3V6K  [C_0402]  165.59 40.73 180 bottom
CD76  1U_0402_6.3V6K  [C_0402]  167.22 42.77 0 bottom
CD77  1U_0402_6.3V6K  [C_0402]  163.1 57.04 90 bottom
CD78  1U_0402_6.3V6K  [C_0402]  171.49 57.96 270 bottom
CD79  1U_0402_6.3V6K  [C_0402]  165.57 46.14 180 bottom
CD80  1U_0402_6.3V6K  [C_0402]  108.29 43.27 0 bottom
CD81  10U_0603_6.3V6M  [C_0603]  107.67 42 180 bottom
CD82  1U_0402_6.3V6K  [C_0402]  108.04 53.05 0 bottom
CD83  1U_0402_6.3V6K  [C_0402]  103.41 57.04 90 bottom
CD84  1U_0402_6.3V6K  [C_0402]  108.8 42.26 0 bottom
CD85  1U_0402_6.3V6K  [C_0402]  113.57 57.96 270 bottom
CD86  1U_0402_6.3V6K  [C_0402]  108.29 44.16 0 bottom
CD87  1U_0402_6.3V6K  [C_0402]  167.22 43.78 0 bottom
CD88  10U_0603_6.3V6M  [C_0603]  166.22 39.46 0 bottom
CH1  12P_0402_50V8J  [C_0402]  123.23 25.19 270 bottom
CH2  12P_0402_50V8J  [C_0402]  123.23 26.29 90 bottom
CH3  1U_0402_6.3V6K  [C_0402]  124.24 24.17 270 bottom
CH4  1U_0402_6.3V6K  [C_0402]  107.94 24.22 180 bottom
CH5  15P_0402_50V8J  [C_0402]  119.67 4.46 90 bottom
CH6  15P_0402_50V8J  [C_0402]  119.67 3.35 270 bottom
CH7  .1U_0402_16V7K  [C_0402]  227.87 12.59 90 bottom
CH8  .1U_0402_16V7K  [C_0402]  235.49 12.59 90 bottom
CH9  0.1U_0402_10V7K  [C_0402]  146.85 5.34 90 bottom
CH11  0.1U_0402_10V7K  [C_0402]  145.83 5.34 90 bottom
CH15  0.1U_0402_10V7K  [C_0402]  148.88 5.35 90 bottom
CH16  0.1U_0402_10V7K  [C_0402]  147.86 5.34 90 bottom
CH19  0.1U_0402_10V7K  [C_0402]  153.45 3.85 270 bottom
CH20  22U_0603_6.3V6M  [C_0603]  110.72 26.38 180 bottom
CH21  1U_0402_6.3V6K  [C_0402]  110.48 25.24 180 bottom
CH25  1U_0402_6.3V6K  [C_0402]  132.07 7.95 180 bottom
CH26  0.1U_0402_10V7K  [C_0402]  132.07 6.19 180 bottom
CH27  0.1U_0402_10V7K  [C_0402]  132.07 7.08 180 bottom
CH28  1U_0402_6.3V6K  [C_0402]  112.76 24.3 180 bottom
CH30  1U_0402_6.3V6K  [C_0402]  130.49 5.3 0 bottom
CH31  0.1U_0402_10V7K  [C_0402]  130.41 4.44 0 bottom
CH32  1U_0402_6.3V6K  [C_0402]  110.48 19.65 180 bottom
CH33  0.1U_0402_10V7K  [C_0402]  110.48 21.68 180 bottom
CH34  0.1U_0402_10V7K  [C_0402]  110.48 20.67 180 bottom
CH35  0.1U_0402_10V7K  [C_0402]  113.02 27.02 180 bottom
CH38  1U_0402_6.3V6K  [C_0402]  134.1 7.95 180 bottom
CH39  0.1U_0402_10V7K  [C_0402]  134.1 6.94 180 bottom
CH40  0.1U_0402_10V7K  [C_0402]  105.6 23.21 180 bottom
CH41  0.1U_0402_10V7K  [C_0402]  137.07 6.95 180 bottom
CH42  1U_0402_6.3V6K  [C_0402]  138.2 5.78 180 bottom
CH44  10U_0603_6.3V6M  [C_0603]  138.76 4.61 180 bottom
CH45  1U_0402_6.3V6K  [C_0402]  137.25 7.95 0 bottom
CH46  22U_0603_6.3V6M  [C_0603]  123.54 2.63 180 bottom
CH47  22U_0603_6.3V6M  [C_0603]  123.54 3.9 180 bottom
CH48  1U_0402_6.3V6K  [C_0402]  123.56 5.05 180 bottom
CH49  1U_0402_6.3V6K  [C_0402]  114.13 28.03 0 bottom
CH50  22U_0603_6.3V6M  [C_0603]  135.67 30.37 90 bottom
CH51  0.1U_0402_10V7K  [C_0402]  131.1 28.58 90 bottom
CH52  0.1U_0402_10V7K  [C_0402]  130.08 28.58 90 bottom
CH53  22U_0603_6.3V6M  [C_0603]  128.81 28.59 90 bottom
CH54  0.1U_0402_10V7K  [C_0402]  135.21 7.95 0 bottom
CH55  22U_0603_6.3V6M  [C_0603]  111.8 4.73 90 bottom
CH56  22U_0603_6.3V6M  [C_0603]  113.07 4.73 90 bottom
CH57  1U_0402_6.3V6K  [C_0402]  114.21 5.22 90 bottom
CH58  1U_0402_6.3V6K  [C_0402]  103.11 27.27 180 bottom
CH59  1U_0402_6.3V6K  [C_0402]  122.21 28.58 90 bottom
CH60  10U_0603_6.3V6M  [C_0603]  102.14 10.06 90 bottom
CH61  1U_0402_6.3V6K  [C_0402]  103.41 10.05 90 bottom
CH62  0.1U_0402_10V7K  [C_0402]  132.12 27.81 90 bottom
CH63  1U_0402_6.3V6K  [C_0402]  115.05 24.99 180 bottom
CH64  0.1U_0402_10V7K  [C_0402]  124.24 11.47 270 bottom
CH65  1U_0402_6.3V6K  [C_0402]  100.16 24.22 0 bottom
CH66  47U_0805_6.3V6M  [C_0805]  145.53 4.13 270 bottom
CH67  47U_0805_6.3V6M  [C_0805]  147.31 4.13 270 bottom
CH68  1U_0402_6.3V6K  [C_0402]  144.05 3.85 270 bottom
CH69  1U_0402_6.3V6K  [C_0402]  108.44 21.68 180 bottom
CH70  47U_0805_6.3V6M  [C_0805]  99.18 23.72 180 bottom
CH71  47U_0805_6.3V6M  [C_0805]  99.18 21.68 180 bottom
CH72  1U_0402_6.3V6K  [C_0402]  99.55 28.54 180 bottom
CH73  47U_0805_6.3V6M  [C_0805]  99.52 31.98 180 bottom
CH74  47U_0805_6.3V6M  [C_0805]  99.52 30.21 180 bottom
CH75  47U_0805_6.3V6M  [C_0805]  141.6 5.55 180 bottom
CH76  47U_0805_6.3V6M  [C_0805]  142.66 4.12 270 bottom
CH77  1U_0402_6.3V6K  [C_0402]  143.09 5.3 0 bottom
CH78  1U_0402_6.3V6K  [C_0402]  134.2 27.76 0 bottom
CH79  1U_0402_6.3V6K  [C_0402]  115.91 22.95 0 bottom
CH80  0.1U_0402_10V7K  [C_0402]  103.11 23.21 180 bottom
CH81  0.1U_0402_10V7K  [C_0402]  103.11 24.21 180 bottom
CH82  0.1U_0402_10V7K  [C_0402]  103.11 25.22 180 bottom
CH83  1U_0402_6.3V6K  [C_0402]  122.67 19.91 180 bottom
CH84  1U_0402_6.3V6K  [C_0402]  124.04 19.91 0 bottom
CH85  1U_0402_6.3V6K  [C_0402]  124.04 20.92 0 bottom
CH86  1U_0402_6.3V6K  [C_0402]  138.42 2.38 180 bottom
CH87  1U_0402_6.3V6K  [C_0402]  138.42 3.4 180 bottom
CH88  1U_0402_6.3V6K  [C_0402]  123.23 28.58 90 bottom
CH89  0.1U_0402_25V6K  [C_0402]  169.91 3.65 180 bottom
CH90  0.1U_0402_25V6K  [C_0402]  189.39 9.72 270 bottom
CH93  1U_0402_6.3V6K  [C_0402]  293.03 13.31 270 bottom
CLIP1  -  [EMIST_SUL-12A2M_1P]  202.8 6.75 270 bottom
CLIP2  -  [EMIST_SUL-12A2M_1P]  195.75 0.9 180 bottom
CLIP3  -  [EMIST_SUL-12A2M_1P]  116 59.6 180 bottom
CLIP4  -  [EMIST_SUL-12A2M_1P]  195.5 59.6 180 bottom
CLIP5  -  [EMIST_SUL-12A2M_1P]  243.75 48.6 180 bottom
CLIP6  -  [EMIST_SUL-12A2M_1P]  169 59.6 180 bottom
CLIP7  -  [EMIST_SUL-12A2M_1P]  89.5 59.6 180 bottom
CLIP8  -  [EMIST_SUL-12A2M_1P]  169.25 0.9 180 bottom
CLIP9  -  [EMIST_SUL-12A2M_1P]  296 17.75 270 bottom
CLIP10  -  [EMIST_SUL-12A2M_1P]  201.1 21.75 270 bottom
CLIP11  -  [EMIST_SUL-12A2M_1P]  201.1 48.25 270 bottom
CLIP12  -  [EMIST_SUL-12A2M_1P]  208.25 35.6 180 bottom
CLIP13  -  [EMIST_SUL-12A2M_1P]  271.25 10.9 180 bottom
CLIP14  -  [EMIST_SUL-12A2M_1P]  245 6.25 270 bottom
CLIP15  -  [EMIST_SUL-12A2M_1P]  69.9 27.75 270 bottom
CLIP17  -  [EMIST_SUL-12A2M_1P]  74.75 8.5 180 bottom
CLIP18  -  [EMIST_SUL-12A2M_1P]  73.75 51.6 180 bottom
CLIP19  -  [EMIST_SUL-12A2M_1P]  296 44.25 270 bottom
CLIP20  -  [EMIST_SUL-12A2M_1P]  270.25 48.6 180 bottom
CLIP21  -  [EMIST_SUL-12A2M_1P]  223.75 1.9 180 bottom
CLIP22  -  [EMIST_SUL-12A2M_1P]  116.25 0.9 180 bottom
CLIP23  -  [EMIST_SUL-12A2M_1P]  142.75 0.9 180 bottom
CLIP24  -  [EMIST_SUL-12A2M_1P]  142.5 59.6 180 bottom
CLRP1  SHORT PADS  [SHORTPADS]  96.35 34.45 270 bottom
CLRP3  SHORT PADS  [SHORTPADS]  293.53 14.64 0 bottom
CS3  0.01U_0402_16V7K  [C_0402]  24.56 38.67 90 bottom
CS4  0.01U_0402_16V7K  [C_0402]  25.58 38.67 90 bottom
CS7  0.01U_0402_16V7K  [C_0402]  26.5 38.67 90 bottom
CS8  0.01U_0402_16V7K  [C_0402]  27.51 38.67 90 bottom
CV1  .1U_0402_16V7K  [C_0402]  22.52 35.22 270 bottom
CV2  .1U_0402_16V7K  [C_0402]  21.5 35.22 270 bottom
CV3  .1U_0402_16V7K  [C_0402]  24.55 35.22 270 bottom
CV4  .1U_0402_16V7K  [C_0402]  23.53 35.22 270 bottom
CV5  .1U_0402_16V7K  [C_0402]  24.17 32.81 270 bottom
CV6  .1U_0402_16V7K  [C_0402]  23.15 32.81 270 bottom
CV7  .1U_0402_16V7K  [C_0402]  26.2 32.81 270 bottom
CV8  .1U_0402_16V7K  [C_0402]  25.18 32.81 270 bottom
CV9  .1U_0402_16V7K  [C_0402]  26.58 35.22 270 bottom
CV10  .1U_0402_16V7K  [C_0402]  25.56 35.22 270 bottom
CZ2  0.1U_0402_25V6  [C_0402]  286.8 47.03 270 bottom
CZ3  0.1U_0402_25V6  [C_0402]  288.83 46.12 90 bottom
CZ4  0.1U_0402_25V6  [C_0402]  282.74 47.03 270 bottom
D1  -  [BAT54CW-7-F_SOT323-3]  246.53 14.9 90 bottom
D3  -  [BAT54CW-7-F_SOT323-3]  256.96 14.13 0 bottom
D4  -  [BAT54CW-7-F_SOT323-3]  259.75 14.13 0 bottom
D13  -  [BAT54CW-7-F_SOT323-3]  33.82 39.14 180 bottom
D18  -  [BAT54CW-7-F_SOT323-3]  29.62 40.05 0 bottom
D19  -  [BAT54CW-7-F_SOT323-3]  11.53 34.64 270 bottom
D20  -  [BAT54CW-7-F_SOT323-3]  14.83 34.64 270 bottom
D21  -  [SDMK0340L-7-F_SOD323-2]  104.37 13.3 0 bottom
D22  -  [SDMK0340L-7-F_SOD323-2]  280.36 88.08 0 bottom
D23  -  [ESD207-B1-02EL_TSLP-2-19-2]  302.96 86.69 270 bottom
DA1  -  [TVNST52302AB0_SOT523-3]  33.06 30.25 0 bottom
DA5  -  [TVNST52302AB0_SOT523-3]  36.1 31.14 0 bottom
DA8  -  [PJSOT24CW_SOT323-3]  14.35 45.56 270 bottom
FD1  -  [FIDUCIAL_C40M80]  3.05 30.66 0 top
FD2  -  [FIDUCIAL_C40M80]  308.39 95.41 0 top
FD3  -  [FIDUCIAL_C40M80]  308.81 96.79 180 bottom
FD4  -  [FIDUCIAL_C40M80]  3.05 30.66 180 bottom
H1  -  [H_4P6]  304.5 100.41 180 bottom
H2  -  [H_4P0X5P0]  298.5 4.41 90 bottom
H3  -  [H_3P7]  81.5 4.41 180 bottom
H4  -  [H_4P6]  72.8 56.95 180 bottom
H5  -  [H_4P6]  4 24.51 180 bottom
H6  -  [H_4P6]  206.5 56.95 270 top
H7  -  [H_4P0N]  53.5 55.4 0 top
H8  -  [H_1P2]  174.32 17.45 0 top
H9  -  [H_1P2]  118.32 17.45 0 top
JAPS1  E-T_6705K-Y18N-00L  [E-T_6705K-Y18N-00L_18P]  38.71 52.62 180 top
JAUD1  ACES_51015-05001-002  [ACES_51015-05001-002_50P]  10.98 57.3 270 bottom
JBAT1  FOX_GS73091-10272M-7H  [FOX_GS73091-10272M-7H_9P]  233.35 40.67 270 bottom
JBT1  ACES_50278-00201-001  [ACES_50278-00201-001_2P]  290.29 8.19 180 bottom
JCAN1  ACES_50406-02071-001  [ACES_50406-02071-001_20P]  204.43 40.75 90 bottom
JDEBUG  ACES_50521-01041-P01  [ACES_50521-01041-P01_10P]  27.22 41.9 90 bottom
JDEG1  ACES_50521-01041-P01  [ACES_50521-01041-P01_10P]  294.97 94.6 0 bottom
JIO1  HRS_FH29DJ-70S-0P2SHW-05  [HRS_FH29DJ-70S-0P2SHW-05_70P-T]  106.3 2.37 180 bottom
JLPDE1  ACES_50521-01041-P01  [ACES_50521-01041-P01_10P]  282.74 74.81 90 bottom
JLVDS1  ACES_50406-03071-001  [ACES_50406-03071-001_30P]  250.25 8.95 0 bottom
JNGFF1  BELLW_80148-1721  [BELLW_80148-1721_67P-T]  29.75 29.4 180 bottom
JNGFF2  BELLW_80149-2021  [BELLW_80149-2021_67P-T]  44.25 9.88 0 bottom
JNGFF3  BELLW_80149-2021  [BELLW_80149-2021_67P-T]  15.25 50.07 0 bottom
JPWR1  ACES_50281-00601-001  [ACES_50281-00601-001_6P-T]  279.63 7.97 180 bottom
JSNR1  E-T_6718K-Y24N-20L  [E-T_6718K-Y24N-20L_24P-T]  279.78 92.48 0 bottom
JSPI1  ACES_50696-0200M-001  [ACES_50696-0200M-001_20P-T]  215.68 5.94 180 bottom
JSPK1  E-T_3703K-F04N-03R  [E-T_3703K-F04N-03R_4P]  44 6.82 180 bottom
JTS1  ACES_50521-0084N-P01  [ACES_50521-0084N-P01_8P]  305.1 88.9 180 bottom
JUSH1  E-T_6705K-Y20N-00L  [E-T_6705K-Y20N-00L_20P]  293.75 50.7 0 bottom
JXDP1  E-T_6601K-Y61N-04L  [E-T_6601K-Y61N-04L_61P]  181.36 3.78 0 top
L1  2.2UH_LQM2MPN2R2NG0L_30%  [MURAT_LQM2MPN2R2NG0L_2P]  150.44 3.14 180 bottom
L2  2.2UH_LQM2MPN2R2NG0L_30%  [MURAT_LQM2MPN2R2NG0L_2P]  100.84 30.07 0 bottom
L3  2.2UH_LQM2MPN2R2NG0L_30%  [MURAT_LQM2MPN2R2NG0L_2P]  139.44 2.94 0 bottom
L10  FBMA-L11-160808-800LMT_0603  [KC_FBMA-L11-160808-800LMT_2P]  300.51 79.34 180 bottom
L11  BLM15PX181SN1D_2P  [MURAT_BLM15PX181SN1D_2P]  33.75 34.94 270 bottom
L12  BLM15PX181SN1D_2P  [MURAT_BLM15PX181SN1D_2P]  32.3 34.94 270 bottom
L13  BLM15PX181SN1D_2P  [MURAT_BLM15PX181SN1D_2P]  35.55 35.87 270 bottom
L14  BLM15PX181SN1D_2P  [MURAT_BLM15PX181SN1D_2P]  37.03 35.86 270 bottom
LH1  2.2UH_LQM21PN2R2MC0D_20%  [MURAT_LQM21PN2R2MC0D_2P]  125.11 2.6 90 bottom
LH2  2.2UH_LQM21PN2R2MC0D_20%  [MURAT_LQM21PN2R2MC0D_2P]  113.94 3.05 180 bottom
LH3  0_0805_5%  [R0805_0OHM]  99.13 25.75 180 bottom
MC1  10P_0402_50V8J  [C_0402]  119.47 23.97 0 bottom
MC2  10P_0402_50V8J  [C_0402]  123.53 12.54 0 bottom
MC5  680P_0402_50V7K  [C_0402]  259.8 12.79 0 bottom
MD1  -  [IP4223CZ6_SO6-6]  300.58 91.69 0 bottom
MD2  -  [IP4223CZ6_SO6-6]  197.46 45.46 0 bottom
MD7  -  [IP4223CZ6_SO6-6]  197.46 50.29 0 bottom
MD14  -  [IP4223CZ6_SO6-6]  199.11 37.53 180 bottom
ML1  DLW21HN900HQ2L_4P  [MURAT_DLW21HN900HQ2L_4P]  197.57 54.54 270 bottom
ML5  DLW21HN900HQ2L_4P  [MURAT_DLW21HN900HQ2L_4P]  28.76 33.75 270 bottom
ML6  DLW21HN900HQ2L_4P  [MURAT_DLW21HN900HQ2L_4P]  47.11 4.83 90 bottom
ML10  DLW21HN900HQ2L_4P  [MURAT_DLW21HN900HQ2L_4P]  199.6 54.54 270 bottom
NOREF  -  []  254.42 5.22 0 top
NOREF#2  -  []  298.5 4.41 0 top
NOREF#3  -  []  4 24.51 0 top
NOREF#4  -  []  174.32 17.45 0 top
NOREF#5  -  []  5.04 49.55 0 top
NOREF#6  -  []  90.28 36.14 0 top
NOREF#7  -  []  304.5 100.41 0 top
NOREF#8  -  []  118.32 17.45 0 top
NOREF#9  -  []  93 -29.5 0 top
NOREF#10  -  []  74.25 25.99 0 top
NOREF#11  -  []  72.8 56.95 0 top
NOREF#12  -  []  81.5 4.41 0 top
NOREF#13  -  []  109.8 36.49 0 top
NOREF#14  -  []  206.5 56.95 0 top
NOREF#15  -  []  112.69 36.2 180 bottom
NOREF#16  -  []  132.64 33.31 180 bottom
NOREF#17  -  []  162.1 101.46 180 bottom
NOREF#18  -  []  45.79 30.27 180 bottom
PC1  100P_0402_50V8J  [C_0402]  244.18 39.97 0 bottom
PC2  100P_0402_50V8J  [C_0402]  244.18 40.99 0 bottom
PC3  100P_0402_50V8J  [C_0402]  240.22 45.31 180 bottom
PC4  1000P_0402_25V8J  [C_0402]  240.22 44.29 180 bottom
PC5  1000P_0402_25V8J  [C_0402]  240.22 46.32 180 bottom
PC6  100P_0402_50V8J  [C_0402]  242.15 38.96 0 bottom
PC8  0.01U_0402_25V7K  [C_0402]  245.22 42.77 270 bottom
PC10  1000P_0402_25V8J  [C_0402]  247.25 42.77 270 bottom
PC11  1000P_0402_25V8J  [C_0402]  275.37 18.08 90 bottom
PC55  33P_0402_50V8J  [C_0402]  237.78 51.96 90 bottom
PC56  33P_0402_50V8J  [C_0402]  243.06 42.92 180 bottom
PC60  0.1U_0402_25V6  [C_0402]  292.53 16.22 180 bottom
PC70  100P_0402_50V8J  [C_0402]  297.85 30.53 90 bottom
PC80  0.1U_0402_25V6  [C_0402]  299.74 22.26 270 bottom
PC108  2200P_0402_50V7K  [C_0402]  187.11 29.76 270 bottom
PC110  0.1U_0402_25V6  [C_0402]  186.09 29.76 270 bottom
PC111  33U_D2_25VM_R60M  [C_D2]  197.85 24.99 180 bottom
PC300  4.7U_0603_6.3V6K  [C_0603]  280.52 33.18 90 bottom
PC303  2200P_0402_50V7K  [C_0402]  280.33 24.27 90 bottom
PC305  0.1U_0402_25V6  [C_0402]  284.57 30.76 0 bottom
PC306  0.1U_0402_25V6  [C_0402]  275.87 30.07 0 bottom
PC307  150U_B2_6.3VM_R35M  [C_B2]  287.56 32.54 270 bottom
PC308  150U_B2_6.3VM_R35M  [C_B2]  274.04 32.67 270 bottom
PC309  680P_0603_50V8J  [C_0603]  285.15 28.22 180 bottom
PC310  680P_0603_50V8J  [C_0603]  275.82 27.78 0 bottom
PC311  4.7U_0603_6.3V6K  [C_0603]  280.26 26.64 180 bottom
PC312  4.7U_0603_6.3V6M  [C_0603]  283.82 32.03 0 bottom
PC313  10U_0805_25V6K  [C_0805]  279.27 24.99 180 bottom
PC314  0.1U_0402_25V6  [C_0402]  281.57 26.89 0 bottom
PC315  10U_0805_25V6K  [C_0805]  281.38 25.49 0 bottom
PC400  0.1U_0402_25V6  [C_0402]  288.28 45.19 0 bottom
PC401  10U_0805_25V6K  [C_0805]  292.3 42.98 270 bottom
PC402  22P_0402_50V8J  [C_0402]  283.93 40.68 0 bottom
PC403  22U_0603_6.3V6M  [C_0603]  287.11 37.13 90 bottom
PC404  0.1U_0402_25V6  [C_0402]  291.89 44.2 0 bottom
PC405  2200P_0402_50V7K  [C_0402]  290.93 43.68 270 bottom
PC406  3300P_0402_50V7-K  [C_0402]  284.83 44.35 270 bottom
PC407  470P_0402_50V7K  [C_0402]  292.79 40.27 180 bottom
PC408  0.1U_0402_25V6  [C_0402]  276.09 45.45 0 bottom
PC409  10U_0805_25V6K  [C_0805]  280.11 43.24 270 bottom
PC410  22P_0402_50V8J  [C_0402]  271.61 40.73 0 bottom
PC411  22U_0603_6.3V6M  [C_0603]  274.91 37.38 90 bottom
PC412  0.1U_0402_25V6  [C_0402]  279.7 44.45 0 bottom
PC413  2200P_0402_50V7K  [C_0402]  278.74 43.94 270 bottom
PC414  3300P_0402_50V7-K  [C_0402]  272.64 44.61 270 bottom
PC415  470P_0402_50V7K  [C_0402]  280.6 40.52 180 bottom
PC500  0.22U_0402_10V6K  [C_0402]  73.26 27.89 180 bottom
PC502  680P_0603_50V7K  [C_0603]  82.2 25.54 270 bottom
PC503  2200P_0402_50V7K  [C_0402]  78.01 20.22 270 bottom
PC504  0.1U_0402_25V6  [C_0402]  78.89 20.22 270 bottom
PC505  0.1U_0603_25V7K  [C_0603]  72.99 19.44 0 bottom
PC506  10U_0805_25V6K  [C_0805]  81.94 21.26 90 bottom
PC507  10U_0805_25V6K  [C_0805]  80.23 21.26 90 bottom
PC508  47P_0402_50V8J  [C_0402]  73.61 23.8 270 bottom
PC509  47U_0805_6.3V6M  [C_0805]  72.68 32.9 90 bottom
PC510  47U_0805_6.3V6M  [C_0805]  81.75 32.55 270 bottom
PC511  22U_0603_6.3V6M  [C_0603]  74.08 35.81 180 bottom
PC512  22U_0603_6.3V6M  [C_0603]  80.52 34.62 0 bottom
PC513  4.7U_0603_6.3V6K  [C_0603]  74.39 21.85 180 bottom
PC514  4.7U_0603_6.3V6K  [C_0603]  76.93 20.01 180 bottom
PC515  10U_0805_25V6K  [C_0805]  190.22 29.71 270 bottom
PC517  10U_0805_25V6K  [C_0805]  191.98 29.71 270 bottom
PC519  0.1U_0402_25V6  [C_0402]  187.02 22.61 90 bottom
PC523  390P_0402_50V7K  [C_0402]  181.43 14.03 0 bottom
PC531  0.022U_0402_25V7K  [C_0402]  180.74 19.82 270 bottom
PC532  680P_0603_50V7K  [C_0603]  186.66 25.37 0 bottom
PC533  6800P_0402_25V7K  [C_0402]  185.46 12.34 90 bottom
PC534  0.22U_0603_16V7K  [C_0603]  189.33 24.02 270 bottom
PC537  0.047U_0402_25V7K  [C_0402]  181.76 19.82 270 bottom
PC538  33P_0402_50V8J  [C_0402]  184.44 14.37 90 bottom
PC539  10U_0805_25V6K  [C_0805]  188.45 29.67 270 bottom
PC540  1000P_0402_50V7K  [C_0402]  188.38 14.37 90 bottom
PC541  47P_0402_50V8J  [C_0402]  187.49 13.25 270 bottom
PC542  330P_0402_50V7K  [C_0402]  180.92 16.06 0 bottom
PC547  0.01U_0402_50V7K  [C_0402]  180.92 17.07 0 bottom
PC549  0.082U_0402_16V7K  [C_0402]  182.9 16.11 90 bottom
PC559  1U_0402_6.3V6K  [C_0402]  192.31 21.13 270 bottom
PC600  0.1U_0402_25V6  [C_0402]  223.05 18.59 270 bottom
PC601  2200P_0402_50V7K  [C_0402]  224.06 18.59 270 bottom
PC602  10U_0805_25V6K  [C_0805]  221.52 18.72 270 bottom
PC603  10U_0805_25V6K  [C_0805]  219.75 18.72 270 bottom
PC604  0.1U_0603_25V7K  [C_0603]  215.68 23.65 0 bottom
PC605  10U_0805_6.3V6K  [C_0805]  217.37 30.57 0 bottom
PC606  10U_0805_6.3V6K  [C_0805]  215.68 29.14 270 bottom
PC607  1U_0603_10V6K  [C_0603]  220.25 21.75 90 bottom
PC609  330U_B2_2.5VM_R9M  [C_B2]  207.57 31.76 180 bottom
PC610  0.033U_0402_16V7K  [C_0402]  220.51 30.12 90 bottom
PC611  1U_0603_10V6K  [C_0603]  221.52 23.14 270 bottom
PC612  680P_0402_50V7K  [C_0402]  219.42 13.96 90 bottom
PC613  0.1U_0402_10V7K  [C_0402]  222.84 27.27 0 bottom
PC614  0.1U_0402_10V7K  [C_0402]  222.84 28.29 0 bottom
PC617  330U_B2_2.5VM_R9M  [C_B2]  208.12 24.27 180 bottom
PC700  0.022U_0603_50V7K  [C_0603]  253.29 25.09 180 bottom
PC701  0.1U_0402_25V6  [C_0402]  256.22 24.44 180 bottom
PC702  1U_0603_25V6K  [C_0603]  249.72 26.83 90 bottom
PC703  0.1U_0402_25V6  [C_0402]  249.77 29.3 0 bottom
PC704  0.1U_0402_25V6  [C_0402]  251.62 28.55 0 bottom
PC705  1U_0603_10V6K  [C_0603]  253.34 34.89 0 bottom
PC706  1U_0805_25V6K  [C_0805]  253.78 29.47 90 bottom
PC707  0.01U_0402_50V7K  [C_0402]  248.65 29.3 180 bottom
PC708  0.047U_0603_25V7K~D  [C_0603]  254.73 32.35 180 bottom
PC709  2200P_0402_50V7K  [C_0402]  264.65 24.4 0 bottom
PC713  10U_0805_25V6K  [C_0805]  268.33 40.23 0 bottom
PC714  10U_0805_25V6K  [C_0805]  268.32 41.94 0 bottom
PC715  100P_0402_50V8J  [C_0402]  243.93 29.81 0 bottom
PC716  100P_0402_50V8J  [C_0402]  243.93 30.83 0 bottom
PC717  10U_0805_25V6K  [C_0805]  268.34 36.79 0 bottom
PC718  0.1U_0603_25V7K  [C_0603]  268.57 43.4 0 bottom
PC719  10U_0805_25V6K  [C_0805]  268.43 46.58 0 bottom
PC720  10U_0805_25V6K  [C_0805]  268.42 44.86 0 bottom
PC721  0.1U_0402_25V6  [C_0402]  248.66 37.89 270 bottom
PC722  1000P_0603_50V7K  [C_0603]  266.15 32.43 270 bottom
PC723  0.1U_0402_25V6  [C_0402]  251.37 38.78 270 bottom
PC724  0.1U_0402_25V6  [C_0402]  251.45 36.92 180 bottom
PC725  0.1U_0402_25V6  [C_0402]  250.48 37.86 90 bottom
PC726  10U_0805_25V6K  [C_0805]  260.7 25.62 180 bottom
PC727  10U_0805_25V6K  [C_0805]  260.7 23.84 180 bottom
PC728  10U_0805_25V6K  [C_0805]  260.7 22.06 180 bottom
PC729  10U_0805_25V6K  [C_0805]  265.69 27.86 90 bottom
PC730  10U_0805_25V6K  [C_0805]  264.55 22.83 0 bottom
PC731  10U_0805_25V6K  [C_0805]  264.51 25.93 0 bottom
PC732  10U_0805_25V6K  [C_0805]  268.33 38.52 0 bottom
PC760  0.1U_0402_25V6  [C_0402]  286.54 15.1 270 bottom
PC800  22U_0603_6.3V6M  [C_0603]  162.09 11.1 270 bottom
PC801  22U_0603_6.3V6M  [C_0603]  163.35 11.1 270 bottom
PC802  22U_0603_6.3V6M  [C_0603]  162.47 20.69 90 bottom
PC803  22U_0603_6.3V6M  [C_0603]  159.8 20.69 90 bottom
PC804  22U_0603_6.3V6M  [C_0603]  160.31 19.59 270 bottom
PC805  22U_0603_6.3V6M  [C_0603]  159.04 19.59 270 bottom
PC806  22U_0603_6.3V6M  [C_0603]  159.36 15.84 0 bottom
PC807  22U_0603_6.3V6M  [C_0603]  160.75 17.11 180 bottom
PC808  22U_0603_6.3V6M  [C_0603]  161.07 13.24 90 bottom
PC809  22U_0603_6.3V6M  [C_0603]  159.8 13.24 90 bottom
PC810  22U_0603_6.3V6M  [C_0603]  164.46 24.54 180 bottom
PC811  22U_0603_6.3V6M  [C_0603]  160.79 11.1 270 bottom
PC812  22U_0603_6.3V6M  [C_0603]  161.12 20.69 90 bottom
PC813  22U_0603_6.3V6M  [C_0603]  164.46 23.28 180 bottom
PC814  1U_0402_6.3V6K  [C_0402]  149.58 8 270 bottom
PC815  1U_0402_6.3V6K  [C_0402]  160.46 7.52 90 bottom
PC816  1U_0402_6.3V6K  [C_0402]  146.07 7.99 270 bottom
PC817  1U_0402_6.3V6K  [C_0402]  144.32 7.99 270 bottom
PC818  1U_0402_6.3V6K  [C_0402]  159.05 6.45 270 bottom
PC819  1U_0402_6.3V6K  [C_0402]  143.46 7.99 270 bottom
PC820  1U_0402_6.3V6K  [C_0402]  147.83 7.99 270 bottom
PC821  1U_0402_6.3V6K  [C_0402]  161.36 7.52 90 bottom
PC822  1U_0402_6.3V6K  [C_0402]  158.18 6.44 270 bottom
PC823  1U_0402_6.3V6K  [C_0402]  159.93 6.45 270 bottom
PC824  1U_0402_6.3V6K  [C_0402]  148.7 8 270 bottom
PC825  1U_0402_6.3V6K  [C_0402]  151.47 7.99 180 bottom
PC826  1U_0402_6.3V6K  [C_0402]  146.95 7.99 270 bottom
PC827  1U_0402_6.3V6K  [C_0402]  141.7 7.99 270 bottom
PC828  1U_0402_6.3V6K  [C_0402]  140.8 7.98 270 bottom
PC829  1U_0402_6.3V6K  [C_0402]  164.07 25.68 180 bottom
PC830  1U_0402_6.3V6K  [C_0402]  164.08 26.55 180 bottom
PC831  0.22U_0402_6.3V6K  [C_0402]  142.58 7.99 270 bottom
PC832  0.22U_0402_6.3V6K  [C_0402]  156.4 6.54 0 bottom
PC833  0.22U_0402_6.3V6K  [C_0402]  152.3 7.98 0 bottom
PC834  0.22U_0402_6.3V6K  [C_0402]  153.52 6.63 0 bottom
PC835  0.22U_0402_6.3V6K  [C_0402]  145.2 7.99 270 bottom
PC836  0.22U_0402_6.3V6K  [C_0402]  159.56 7.52 90 bottom
PC840  33P_0402_50V8J  [C_0402]  153.5 4.79 0 bottom
PC900  100P_0402_50V8J  [C_0402]  265.52 17.62 0 bottom
PC901  0.01UF_0402_25V7K  [C_0402]  264.4 17.62 180 bottom
PC902  0.1U_0402_10V7K  [C_0402]  281.47 15.28 270 bottom
PC903  1000P_0402_50V7K  [C_0402]  269.83 14.06 0 bottom
PC904  1U_0603_10V6K  [C_0603]  285.46 15.04 270 bottom
PC905  0.1U_0402_10V7K  [C_0402]  262.62 17.11 180 bottom
PC906  0.1U_0402_25V6  [C_0402]  262.62 14.06 180 bottom
PC907  1U_0603_10V6K  [C_0603]  267.31 12.67 180 bottom
PD1  -  [SDMK0340L-7-F_SOD323-2]  239.56 27.96 270 bottom
PD3  -  [PJSOT24CW_SOT323-3]  242.1 53.85 180 bottom
PD4  -  [PJSOT24CW_SOT323-3]  239.56 53.85 180 bottom
PD700  -  [BAT54CW_SOT323-3]  254.33 27.47 270 bottom
PD701  -  [SDMK0340L-7-F_SOD323-2]  285.82 18.92 270 bottom
PH503  10KB_0402_5%_ERTJ0ER103J  [R_0402]  177.39 20.35 0 bottom
PH504  470K_0402_5%_ TSM0B474J4702RE  [R_0402]  181.14 29.74 90 bottom
PJ300  -  [JUMP_43X118]  270.89 33.31 180 bottom
PJ301  -  [JUMP_43X118]  290.72 33.81 0 bottom
PJ600  -  [JUMP_43X118]  206.67 27.61 90 bottom
PJ602  -  [JUMP_43X39]  215.68 30.62 90 bottom
PJP400  -  [JUMP_43X39]  285.49 37.76 180 bottom
PJP401  -  [JUMP_43X39]  273.29 38.02 180 bottom
PJP500  -  [JUMP_43X118]  77.22 36.44 90 bottom
PJP701  PAD-OPEN1x1m  [JUMP_43X39]  244.84 35.45 180 bottom
PL1  HCB2012KF-121T50_0805  [TAI-T_HCB2012KF-121T50_2P]  242.18 44.3 0 bottom
PL300  HCB2012KF-121T50_0805  [TAI-T_HCB2012KF-121T50_2P]  279.44 20.94 90 bottom
PL301  2.2UH_MMD-06BD-2R2M-X2L_7A_20%  [MAG_MMD-06BD-2R2M-X2L_2P]  290.18 28.61 270 bottom
PL302  2.2UH_MMD-06BD-2R2M-X2L_7A_20%  [MAG_MMD-06BD-2R2M-X2L_2P]  270.39 23.05 90 bottom
PL304  HCB2012KF-121T50_0805  [TAI-T_HCB2012KF-121T50_2P]  281.34 20.19 90 bottom
PL400  HCB1608KF-121T30_0603  [TAI-T_HCB1608KF-121T3_L0603_2P]  290.4 45.42 0 bottom
PL401  2.2UH_1239AS-H-2R2N-P2_1.3A_30%  [TOKO_1239AS-H-2R2N-P2_2P]  289.18 39.24 270 bottom
PL402  HCB1608KF-121T30_0603  [TAI-T_HCB1608KF-121T3_L0603_2P]  278.21 45.67 0 bottom
PL403  2.2UH_1239AS-H-2R2N-P2_1.3A_30%  [TOKO_1239AS-H-2R2N-P2_2P]  276.99 39.5 270 bottom
PL500  HCB2012KF-121T50_0805  [TAI-T_HCB2012KF-121T50_2P]  82.12 19.82 180 bottom
PL501  1UH_MMD-06BD-1R0M-X2L_9A_20%  [MAG_MMD-06BD-1R0M-X2L_2P]  77.19 27.07 90 bottom
PL503  FBMA-L11-453215-800LMA90T_1812  [L_1812-1806]  194.1 30.86 0 bottom
PL504  0.22UH_MMD-06BD-R22MEV1L_21A_20%  [MAG_MMD-06BD-R22MEV1L_4P]  180.06 24.6 180 bottom
PL600  HCB2012KF-121T50_0805  [TAI-T_HCB2012KF-121T50_2P]  224.81 20.16 180 bottom
PL601  2.2UH_MMD-06BD-2R2M-X2L_7A_20%  [MAG_MMD-06BD-2R2M-X2L_2P]  206.92 19.14 0 bottom
PL700  FBMA-L11-201209-121LMA50T_0805  [KC_FBMA-L11-201209-121LMA50_2P]  262.72 21.91 90 bottom
PL701  2.2UH_MMD-06BD-2R2M-X2L_7A_20%  [MAG_MMD-06BD-2R2M-X2L_2P]  261.66 35.86 90 bottom
PQ1  -  [AON7405_DFN8-5]  248.65 46.59 270 bottom
PQ2  -  [AON7405_DFN8-5]  250.48 44.65 90 bottom
PQ4  -  [AON7405_DFN8-5]  276.98 13.3 90 bottom
PQ5  -  [AON7405_DFN8-5]  276.73 17.14 90 bottom
PQ6  -  [DMN65D8LW-7_SOT323-3]  238.6 22.83 90 bottom
PQ7  -  [DMN65D8LW-7_SOT323-3]  78.18 18.19 180 bottom
PQ8  -  [SI2303CDS-T1-GE3_SOT23-3]  237.5 31.59 90 bottom
PQ30  -  [DMN65D8LW-7_SOT323-3]  239.96 35.34 0 bottom
PQ31  -  [DMN65D8LW-7_SOT323-3]  239.84 38.68 0 bottom
PQ32  -  [DMN65D8LW-7_SOT323-3]  226.87 33.38 270 bottom
PQ34  -  [DMN65D8LW-7_SOT323-3]  252.28 42.38 180 bottom
PQ51  -  [DMN65D8LW-7_SOT323-3]  272 18.96 90 bottom
